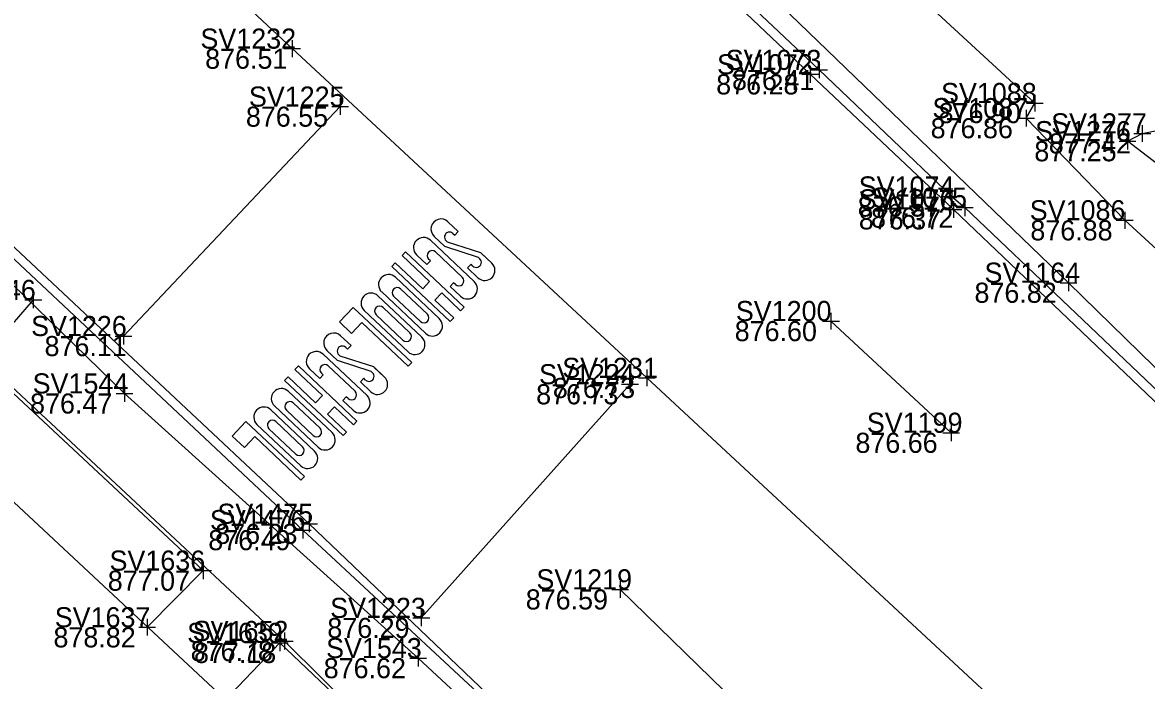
# Model space of a CAD drawing. Extents: x 1480001 to 1480402, y 379235 to 379603.
# Drawn here: x 1480268.3 to 1480335.4, y 379281.8 to 379321.1 of the extents above; entities that cross this region are included whole.
import ezdxf

# ---------------------------------------------------------------- set-up
doc = ezdxf.new("R2010")
doc.units = 0
for name, color, linetype in [('PM_P_CL_Double_Solid', 7, 'Continuous'), ('PM_X_Cells', 7, 'Continuous'), ('PM_X_Lane_Line', 7, 'Continuous'), ('PM_X_Stop_Line', 7, 'Continuous'), ('PV_X_Curb', 7, 'Continuous'), ('PV_X_Driveway', 7, 'Continuous'), ('PV_X_Steps', 7, 'Continuous'), ('PV_X_Walk', 7, 'Continuous'), ('RD_X_Concrete_Pad', 7, 'Continuous'), ('SV_X_Shot_Marker', 7, 'Continuous'), ('SV_X_Text_Elevation', 7, 'Continuous'), ('SV_X_Text_Name', 7, 'Continuous'), ('UT_X_Water', 7, 'Continuous')]:
    doc.layers.add(name, color=color, linetype=linetype)

msp = doc.modelspace()

# ---------------------------------------------------------------- linework, layer by layer
at = {"layer": 'PM_P_CL_Double_Solid'}
msp.add_lwpolyline([(1480349.171, 379259.048), (1480326.954, 379280.06), (1480305.568, 379299.916), (1480284.393, 379319.578), (1480263.301, 379339.268), (1480242.575, 379359.213), (1480224.612, 379376.165), (1480208.191, 379391.527)], dxfattribs=at)
at = {"layer": 'PM_X_Cells'}
for p, q in [((1480293.697, 379309.242), (1480294.315, 379308.658)), ((1480292.653, 379308.137), (1480295.271, 379305.665)), ((1480292.873, 379308.369), (1480293.515, 379307.763)), ((1480294, 379308.543), (1480294.109, 379308.44)), ((1480294.315, 379308.658), (1480294.109, 379308.44)), ((1480291.173, 379307.443), (1480290.968, 379307.225)), ((1480291.173, 379307.443), (1480294.664, 379304.148)), ((1480292.956, 379307.438), (1480294.556, 379305.928)), ((1480295.515, 379307.113), (1480293.515, 379307.763)), ((1480293.588, 379308.107), (1480293.672, 379308.027)), ((1480295.672, 379307.377), (1480293.672, 379308.027)), ((1480290.556, 379306.789), (1480290.35, 379306.571)), ((1480290.556, 379306.789), (1480292.192, 379305.244)), ((1480290.968, 379307.225), (1480292.604, 379305.68)), ((1480291.829, 379307.264), (1480292.448, 379306.68)), ((1480292.448, 379306.68), (1480292.653, 379306.899)), ((1480292.653, 379306.899), (1480292.544, 379307.002)), ((1480295.515, 379307.113), (1480295.599, 379307.033)), ((1480295.672, 379307.377), (1480296.314, 379306.771)), ((1480296.314, 379306.771), (1480295.696, 379307.354)), ((1480290.24, 379306.454), (1480290.24, 379306.454)), ((1480290.35, 379306.571), (1480293.84, 379303.276)), ((1480294.873, 379306.481), (1480295.079, 379306.7)), ((1480295.491, 379305.898), (1480294.873, 379306.481)), ((1480295.188, 379306.597), (1480295.079, 379306.7)), ((1480290.566, 379305.926), (1480293.184, 379303.455)), ((1480292.604, 379305.68), (1480292.192, 379305.244)), ((1480293.829, 379305.376), (1480294.035, 379305.594)), ((1480294.144, 379305.491), (1480294.035, 379305.594)), ((1480289.523, 379304.821), (1480292.141, 379302.349)), ((1480289.743, 379305.053), (1480292.36, 379302.582)), ((1480290.458, 379304.791), (1480292.057, 379303.281)), ((1480290.869, 379305.227), (1480292.469, 379303.717)), ((1480293.331, 379304.994), (1480292.919, 379304.558)), ((1480293.331, 379304.994), (1480294.458, 379303.93)), ((1480293.829, 379305.376), (1480294.447, 379304.793)), ((1480288.043, 379304.127), (1480287.219, 379303.255)), ((1480288.043, 379304.127), (1480291.534, 379300.832)), ((1480289.826, 379304.122), (1480291.426, 379302.612)), ((1480292.919, 379304.558), (1480294.046, 379303.494)), ((1480294.664, 379304.148), (1480294.458, 379303.93)), ((1480288.699, 379303.948), (1480291.317, 379301.477)), ((1480289.414, 379303.686), (1480291.014, 379302.176)), ((1480294.046, 379303.494), (1480293.84, 379303.276)), ((1480287.219, 379303.255), (1480287.947, 379302.568)), ((1480288.564, 379303.223), (1480287.947, 379302.568)), ((1480288.564, 379303.223), (1480291.328, 379300.614)), ((1480293.73, 379303.159), (1480293.73, 379303.159)), ((1480287.294, 379302.434), (1480287.912, 379301.851)), ((1480286.47, 379301.562), (1480287.113, 379300.955)), ((1480287.597, 379301.736), (1480287.706, 379301.633)), ((1480287.912, 379301.851), (1480287.706, 379301.633)), ((1480286.25, 379301.329), (1480288.868, 379298.858)), ((1480289.112, 379300.305), (1480287.113, 379300.955)), ((1480287.185, 379301.299), (1480287.269, 379301.22)), ((1480289.269, 379300.57), (1480287.269, 379301.22)), ((1480291.534, 379300.832), (1480291.328, 379300.614)), ((1480284.771, 379300.636), (1480284.565, 379300.418)), ((1480284.565, 379300.418), (1480286.201, 379298.873)), ((1480284.771, 379300.636), (1480288.261, 379297.341)), ((1480285.427, 379300.457), (1480286.045, 379299.873)), ((1480286.045, 379299.873), (1480286.251, 379300.091)), ((1480286.251, 379300.091), (1480286.141, 379300.194)), ((1480286.553, 379300.63), (1480288.153, 379299.12)), ((1480289.112, 379300.305), (1480289.197, 379300.226)), ((1480289.269, 379300.57), (1480289.911, 379299.963)), ((1480289.911, 379299.963), (1480289.293, 379300.547)), ((1480283.837, 379299.647), (1480283.837, 379299.647)), ((1480284.153, 379299.981), (1480283.947, 379299.763)), ((1480283.947, 379299.763), (1480287.437, 379296.468)), ((1480284.153, 379299.981), (1480285.789, 379298.437)), ((1480288.47, 379299.674), (1480288.676, 379299.892)), ((1480289.088, 379299.091), (1480288.47, 379299.674)), ((1480288.785, 379299.789), (1480288.676, 379299.892)), ((1480284.163, 379299.119), (1480286.781, 379296.647)), ((1480286.201, 379298.873), (1480285.789, 379298.437)), ((1480287.426, 379298.569), (1480287.632, 379298.787)), ((1480287.741, 379298.684), (1480287.632, 379298.787)), ((1480283.34, 379298.246), (1480285.957, 379295.775)), ((1480284.466, 379298.42), (1480286.066, 379296.91)), ((1480286.928, 379298.187), (1480286.516, 379297.75)), ((1480286.928, 379298.187), (1480288.055, 379297.123)), ((1480287.426, 379298.569), (1480288.044, 379297.985)), ((1480283.12, 379298.013), (1480285.738, 379295.542)), ((1480284.055, 379297.984), (1480285.654, 379296.473)), ((1480286.516, 379297.75), (1480287.643, 379296.686)), ((1480281.64, 379297.32), (1480280.816, 379296.447)), ((1480281.64, 379297.32), (1480285.131, 379294.025)), ((1480282.296, 379297.141), (1480284.914, 379294.669)), ((1480283.011, 379296.878), (1480284.611, 379295.368)), ((1480283.423, 379297.315), (1480285.023, 379295.804)), ((1480288.261, 379297.341), (1480288.055, 379297.123)), ((1480280.816, 379296.447), (1480281.544, 379295.761)), ((1480282.161, 379296.415), (1480281.544, 379295.761)), ((1480282.161, 379296.415), (1480284.925, 379293.807)), ((1480287.327, 379296.352), (1480287.327, 379296.352)), ((1480287.643, 379296.686), (1480287.437, 379296.468)), ((1480285.131, 379294.025), (1480284.925, 379293.807))]:
    msp.add_line(p, q, dxfattribs=at)
for centre, radius, start, end in [((1480293.285, 379308.806), 0.6, 46.64839, 226.64839), ((1480292.241, 379307.7), 0.6, 46.64839, 226.64537), ((1480293.794, 379308.325), 0.3, 46.64839, 226.64845), ((1480292.75, 379307.22), 0.3, 46.64839, 226.64537), ((1480295.394, 379306.815), 0.3, 226.64839, 46.64845), ((1480295.903, 379306.334), 0.6, 226.64839, 46.64839), ((1480290.154, 379305.49), 0.6, 46.64839, 226.64537), ((1480294.35, 379305.709), 0.3, 226.65142, 46.64839), ((1480294.859, 379305.229), 0.6, 226.65142, 46.64839), ((1480289.111, 379304.384), 0.6, 46.64839, 226.64537), ((1480290.663, 379305.009), 0.3, 46.64839, 226.64537), ((1480289.62, 379303.904), 0.3, 46.64839, 226.64537), ((1480292.263, 379303.499), 0.3, 226.65142, 46.64839), ((1480292.772, 379303.018), 0.6, 226.65142, 46.64839), ((1480286.882, 379301.998), 0.6, 46.64839, 226.64839), ((1480291.22, 379302.394), 0.3, 226.65142, 46.64839), ((1480291.729, 379301.913), 0.6, 226.65142, 46.64839), ((1480285.838, 379300.893), 0.6, 46.64839, 226.64537), ((1480287.391, 379301.518), 0.3, 46.64839, 226.64845), ((1480286.347, 379300.412), 0.3, 46.64839, 226.64537), ((1480288.991, 379300.007), 0.3, 226.64839, 46.64845), ((1480289.5, 379299.527), 0.6, 226.64839, 46.64839), ((1480283.752, 379298.682), 0.6, 46.64839, 226.64537), ((1480287.947, 379298.902), 0.3, 226.65142, 46.64839), ((1480288.456, 379298.422), 0.6, 226.65142, 46.64839), ((1480282.708, 379297.577), 0.6, 46.64839, 226.64537), ((1480284.261, 379298.202), 0.3, 46.64839, 226.64537), ((1480283.217, 379297.097), 0.3, 46.64839, 226.64537), ((1480285.86, 379296.692), 0.3, 226.65142, 46.64839), ((1480286.369, 379296.211), 0.6, 226.65142, 46.64839), ((1480284.817, 379295.586), 0.3, 226.65142, 46.64839), ((1480285.326, 379295.106), 0.6, 226.65142, 46.64839)]:
    msp.add_arc(centre, radius, start, end, dxfattribs=at)
at = {"layer": 'PM_X_Lane_Line'}
for p, q in [((1480323.741, 379296.64), (1480316.564, 379303.311)), ((1480303.976, 379287.288), (1480310.954, 379280.501))]:
    msp.add_line(p, q, dxfattribs=at)
at = {"layer": 'PM_X_Stop_Line'}
for p, q in [((1480287.258, 379316.117), (1480274.332, 379302.416)), ((1480292.11, 379285.585), (1480304.569, 379299.538))]:
    msp.add_line(p, q, dxfattribs=at)
at = {"layer": 'PV_X_Curb'}
for points in [[(1480221.495, 379406.235), (1480232.955, 379395.538), (1480249.633, 379380.044), (1480261.648, 379368.645), (1480263.97, 379366.423), (1480266.337, 379364.241), (1480284.168, 379347.237), (1480298.679, 379333.414), (1480300.396, 379332.229), (1480315.326, 379318.045), (1480323.87, 379309.98), (1480343.087, 379291.663), (1480360.248, 379275.585)], [(1480221.908, 379406.565), (1480233.156, 379396.15), (1480249.934, 379380.311), (1480262.014, 379368.886), (1480262.346, 379369.254), (1480264.513, 379367.165), (1480266.627, 379365.06), (1480266.41, 379364.736), (1480284.493, 379347.537), (1480298.919, 379333.838), (1480300.736, 379332.585), (1480315.855, 379318.308), (1480323.784, 379310.749), (1480324.548, 379310.084), (1480343.241, 379292.305), (1480360.288, 379276.242)], [(1480332.565, 379246.096), (1480328.494, 379249.894), (1480327.862, 379250.385), (1480312.733, 379264.825), (1480299.577, 379277.28), (1480299.42, 379277.447), (1480285.033, 379290.826), (1480266.518, 379308.208), (1480264.058, 379310.698), (1480249.543, 379324.24), (1480247.919, 379326.036), (1480238.925, 379334.096), (1480238.586, 379333.852), (1480236.341, 379335.947), (1480234.187, 379337.989), (1480234.328, 379338.207), (1480233.297, 379339.4), (1480215.447, 379356.074)], [(1480332.882, 379246.442), (1480328.343, 379250.587), (1480312.97, 379265.236), (1480299.564, 379277.688), (1480285.409, 379291.203), (1480266.888, 379308.553), (1480264.304, 379310.926), (1480249.8, 379324.506), (1480248.109, 379326.126), (1480239.302, 379334.68), (1480237.065, 379336.683), (1480233.83, 379339.39), (1480215.875, 379356.288)]]:
    msp.add_lwpolyline(points, dxfattribs=at)
at = {"layer": 'PV_X_Driveway'}
msp.add_lwpolyline([(1480353.09, 379299.613), (1480334.27, 379314.052), (1480335.151, 379314.518), (1480352.114, 379317.984), (1480349.253, 379319.497), (1480351.705, 379323.454), (1480355.715, 379321.036), (1480370.316, 379318.109)], dxfattribs=at)
at = {"layer": 'PV_X_Steps'}
for points in [[(1480263.984, 379296.161), (1480267.157, 379299.539), (1480279.089, 379288.407), (1480275.743, 379285.025)], [(1480280.341, 379280.616), (1480283.659, 379284.091), (1480295.222, 379273.109), (1480291.804, 379269.54)]]:
    msp.add_lwpolyline(points, dxfattribs=at)
at = {"layer": 'PV_X_Walk'}
for points in [[(1480355.123, 379297.828), (1480351.285, 379293.6), (1480334.098, 379309.328), (1480328.212, 379315.428), (1480328.737, 379316.329), (1480319.905, 379324.485), (1480307.606, 379335.13), (1480302.895, 379338.359), (1480281.823, 379358.406), (1480285.611, 379363.387), (1480280.441, 379367.109), (1480277.224, 379362.834), (1480260.819, 379378.019), (1480244.572, 379393.153), (1480235.613, 379401.335), (1480215.341, 379421.047)], [(1480327.959, 379242.083), (1480313.163, 379256.356), (1480297.576, 379270.674), (1480283.951, 379284.205), (1480267.344, 379299.69), (1480258.509, 379307.782), (1480244.036, 379321.372), (1480229.243, 379335.021), (1480213.414, 379349.982), (1480196.806, 379366.202), (1480192.296, 379370.271), (1480186.385, 379375.802), (1480181.8, 379379.27), (1480179.258, 379381.212), (1480177.445, 379382.131), (1480174.921, 379382.868), (1480171.98, 379383.537), (1480169.491, 379383.403), (1480167.014, 379382.902), (1480162.891, 379380.83), (1480161.298, 379379.691), (1480158.915, 379377.808)]]:
    msp.add_lwpolyline(points, dxfattribs=at)
at = {"layer": 'RD_X_Concrete_Pad'}
msp.add_lwpolyline([(1480285.873, 379260.463), (1480292.461, 379269.459), (1480263.894, 379296.102), (1480254.759, 379289.34)], dxfattribs=at)
at = {"layer": 'SV_X_Shot_Marker'}
for p, q in [((1480283.893, 379319.578), (1480284.893, 379319.578)), ((1480284.393, 379320.078), (1480284.393, 379319.078)), ((1480284.393, 379319.578), (1480284.393, 379319.578)), ((1480315.326, 379318.545), (1480315.326, 379317.545)), ((1480315.355, 379318.308), (1480316.355, 379318.308)), ((1480315.855, 379318.808), (1480315.855, 379317.808)), ((1480315.855, 379318.308), (1480315.855, 379318.308)), ((1480314.826, 379318.045), (1480315.826, 379318.045)), ((1480315.326, 379318.045), (1480315.326, 379318.045)), ((1480287.258, 379316.617), (1480287.258, 379315.617)), ((1480328.237, 379316.329), (1480329.237, 379316.329)), ((1480328.737, 379316.829), (1480328.737, 379315.829)), ((1480328.737, 379316.329), (1480328.737, 379316.329)), ((1480286.758, 379316.117), (1480287.758, 379316.117)), ((1480287.258, 379316.117), (1480287.258, 379316.117)), ((1480328.212, 379315.928), (1480328.212, 379314.928)), ((1480327.712, 379315.428), (1480328.712, 379315.428)), ((1480328.212, 379315.428), (1480328.212, 379315.428)), ((1480335.151, 379315.018), (1480335.151, 379314.018)), ((1480334.27, 379314.552), (1480334.27, 379313.552)), ((1480334.651, 379314.518), (1480335.651, 379314.518)), ((1480335.151, 379314.518), (1480335.151, 379314.518)), ((1480333.77, 379314.052), (1480334.77, 379314.052)), ((1480334.27, 379314.052), (1480334.27, 379314.052)), ((1480323.784, 379311.249), (1480323.784, 379310.249)), ((1480323.284, 379310.749), (1480324.284, 379310.749)), ((1480323.784, 379310.749), (1480323.784, 379310.749)), ((1480323.87, 379310.48), (1480323.87, 379309.48)), ((1480324.548, 379310.584), (1480324.548, 379309.584)), ((1480323.37, 379309.98), (1480324.37, 379309.98)), ((1480323.87, 379309.98), (1480323.87, 379309.98)), ((1480324.048, 379310.084), (1480325.048, 379310.084)), ((1480324.548, 379310.084), (1480324.548, 379310.084)), ((1480334.098, 379309.828), (1480334.098, 379308.828)), ((1480333.598, 379309.328), (1480334.598, 379309.328)), ((1480334.098, 379309.328), (1480334.098, 379309.328)), ((1480330.745, 379306.101), (1480330.745, 379305.101)), ((1480330.245, 379305.601), (1480331.245, 379305.601)), ((1480330.745, 379305.601), (1480330.745, 379305.601)), ((1480268.947, 379305.072), (1480268.947, 379304.072)), ((1480268.447, 379304.572), (1480269.447, 379304.572)), ((1480268.947, 379304.572), (1480268.947, 379304.572)), ((1480316.564, 379303.811), (1480316.564, 379302.811)), ((1480274.332, 379302.916), (1480274.332, 379301.916)), ((1480316.064, 379303.311), (1480317.064, 379303.311)), ((1480316.564, 379303.311), (1480316.564, 379303.311)), ((1480273.832, 379302.416), (1480274.832, 379302.416)), ((1480274.332, 379302.416), (1480274.332, 379302.416)), ((1480305.568, 379300.416), (1480305.568, 379299.416)), ((1480274.385, 379299.487), (1480274.385, 379298.487)), ((1480304.069, 379299.538), (1480305.069, 379299.538)), ((1480304.569, 379300.038), (1480304.569, 379299.038)), ((1480304.569, 379299.538), (1480304.569, 379299.538)), ((1480305.068, 379299.916), (1480306.068, 379299.916)), ((1480305.568, 379299.916), (1480305.568, 379299.916)), ((1480273.885, 379298.987), (1480274.885, 379298.987)), ((1480274.385, 379298.987), (1480274.385, 379298.987)), ((1480323.741, 379297.14), (1480323.741, 379296.14)), ((1480323.241, 379296.64), (1480324.241, 379296.64)), ((1480323.741, 379296.64), (1480323.741, 379296.64)), ((1480285.409, 379291.703), (1480285.409, 379290.703)), ((1480284.533, 379290.826), (1480285.533, 379290.826)), ((1480284.909, 379291.203), (1480285.909, 379291.203)), ((1480285.033, 379291.326), (1480285.033, 379290.326)), ((1480285.033, 379290.826), (1480285.033, 379290.826)), ((1480285.409, 379291.203), (1480285.409, 379291.203)), ((1480279.089, 379288.907), (1480279.089, 379287.907)), ((1480278.589, 379288.407), (1480279.589, 379288.407)), ((1480279.089, 379288.407), (1480279.089, 379288.407)), ((1480303.976, 379287.788), (1480303.976, 379286.788)), ((1480303.476, 379287.288), (1480304.476, 379287.288)), ((1480303.976, 379287.288), (1480303.976, 379287.288)), ((1480292.11, 379286.085), (1480292.11, 379285.085)), ((1480275.743, 379285.525), (1480275.743, 379284.525)), ((1480291.61, 379285.585), (1480292.61, 379285.585)), ((1480292.11, 379285.585), (1480292.11, 379285.585)), ((1480275.243, 379285.025), (1480276.243, 379285.025)), ((1480275.743, 379285.025), (1480275.743, 379285.025)), ((1480283.951, 379284.705), (1480283.951, 379283.705)), ((1480283.159, 379284.091), (1480284.159, 379284.091)), ((1480283.451, 379284.205), (1480284.451, 379284.205)), ((1480283.659, 379284.591), (1480283.659, 379283.591)), ((1480283.659, 379284.091), (1480283.659, 379284.091)), ((1480283.951, 379284.205), (1480283.951, 379284.205)), ((1480291.915, 379283.682), (1480291.915, 379282.682)), ((1480291.415, 379283.182), (1480292.415, 379283.182)), ((1480291.915, 379283.182), (1480291.915, 379283.182))]:
    msp.add_line(p, q, dxfattribs=at)
at = {"layer": 'UT_X_Water'}
msp.add_line((1480268.947, 379304.572), (1480263.602, 379298.462), dxfattribs=at)
for points in [[(1480212.628, 379415.684), (1480231.592, 379398.237), (1480249.493, 379381.828), (1480253.44, 379378.963), (1480259.284, 379374.539), (1480264.171, 379372.865), (1480269.434, 379369.248), (1480270.598, 379368.157), (1480270.755, 379365.904), (1480271.186, 379363.733), (1480285.468, 379347.959), (1480298.848, 379335.614), (1480313.013, 379322.705), (1480330.745, 379305.601), (1480344.344, 379292.312), (1480351.783, 379285.136)], [(1480327.263, 379249.797), (1480312.798, 379263.799), (1480291.915, 379283.182), (1480274.385, 379298.987), (1480265.401, 379307.725), (1480264.495, 379308.458), (1480240.472, 379331.084), (1480234.677, 379335.863), (1480225.088, 379345.601), (1480208.322, 379361.342)]]:
    msp.add_lwpolyline(points, dxfattribs=at)

# ---------------------------------------------------------------- texts
at = {"layer": 'SV_X_Text_Elevation'}
for s, p in [('876.51', (1480279.205, 379318.378)), ('876.41', (1480310.658, 379317.108)), ('876.28', (1480309.714, 379316.845)), ('876.90', (1480322.992, 379315.129)), ('876.55', (1480281.636, 379314.917)), ('876.86', (1480322.515, 379314.228)), ('877.42', (1480329.567, 379313.318)), ('877.25', (1480328.705, 379312.852)), ('876.57', (1480318.162, 379309.549)), ('876.37', (1480318.229, 379308.78)), ('876.72', (1480318.955, 379308.884)), ('876.88', (1480328.467, 379308.128)), ('876.82', (1480325.133, 379304.401)), ('876.60', (1480310.819, 379302.111)), ('876.11', (1480269.617, 379301.216)), ('876.73', (1480298.966, 379298.338)), ('876.73', (1480299.965, 379298.716)), ('876.47', (1480268.754, 379297.787)), ('876.66', (1480318.025, 379295.44)), ('876.49', (1480279.392, 379289.626)), ('876.23', (1480279.806, 379290.003)), ('877.07', (1480273.392, 379287.207)), ('876.59', (1480298.345, 379286.088)), ('876.29', (1480286.498, 379284.385)), ('878.82', (1480270.15, 379283.825)), ('876.78', (1480278.339, 379283.005)), ('877.18', (1480278.539, 379282.891)), ('876.62', (1480286.284, 379281.982))]:
    msp.add_text(s, height=1.2, dxfattribs=at).set_placement(p)
at = {"layer": 'SV_X_Text_Name'}
for s, p in [('SV1232', (1480278.923, 379319.578)), ('SV1073', (1480310.281, 379318.308)), ('SV1072', (1480309.762, 379318.045)), ('SV1088', (1480323.135, 379316.329)), ('SV1225', (1480281.817, 379316.117)), ('SV1087', (1480322.619, 379315.428)), ('SV1277', (1480329.71, 379314.518)), ('SV1276', (1480328.753, 379314.052)), ('SV1074', (1480318.22, 379310.749)), ('SV1076', (1480318.221, 379309.98)), ('SV1075', (1480318.974, 379310.084)), ('SV1086', (1480328.43, 379309.328)), ('SV1164', (1480325.729, 379305.601)), ('SV1546', (1480263.383, 379304.572)), ('SV1200', (1480310.886, 379303.311)), ('SV1226', (1480268.815, 379302.416)), ('SV1224', (1480299.137, 379299.538)), ('SV1231', (1480300.523, 379299.916)), ('SV1544', (1480268.906, 379298.987)), ('SV1199', (1480318.706, 379296.64)), ('SV1476', (1480279.488, 379290.826)), ('SV1475', (1480279.939, 379291.203)), ('SV1636', (1480273.496, 379288.407)), ('SV1219', (1480298.979, 379287.288)), ('SV1223', (1480286.669, 379285.585)), ('SV1637', (1480270.226, 379285.025)), ('SV1639', (1480278.132, 379284.091)), ('SV1652', (1480278.462, 379284.205)), ('SV1543', (1480286.426, 379283.182))]:
    msp.add_text(s, height=1.2, dxfattribs=at).set_placement(p)

doc.saveas('drawing.dxf')
